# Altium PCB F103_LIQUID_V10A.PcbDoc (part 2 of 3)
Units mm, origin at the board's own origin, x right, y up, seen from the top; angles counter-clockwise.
Board outline 150.1 x 90.1 mm, 2 copper layers (TOP, BOTTOM), stack 1.6 mm thick; 78 components, 80 nets, 341 pads, 418 vias.
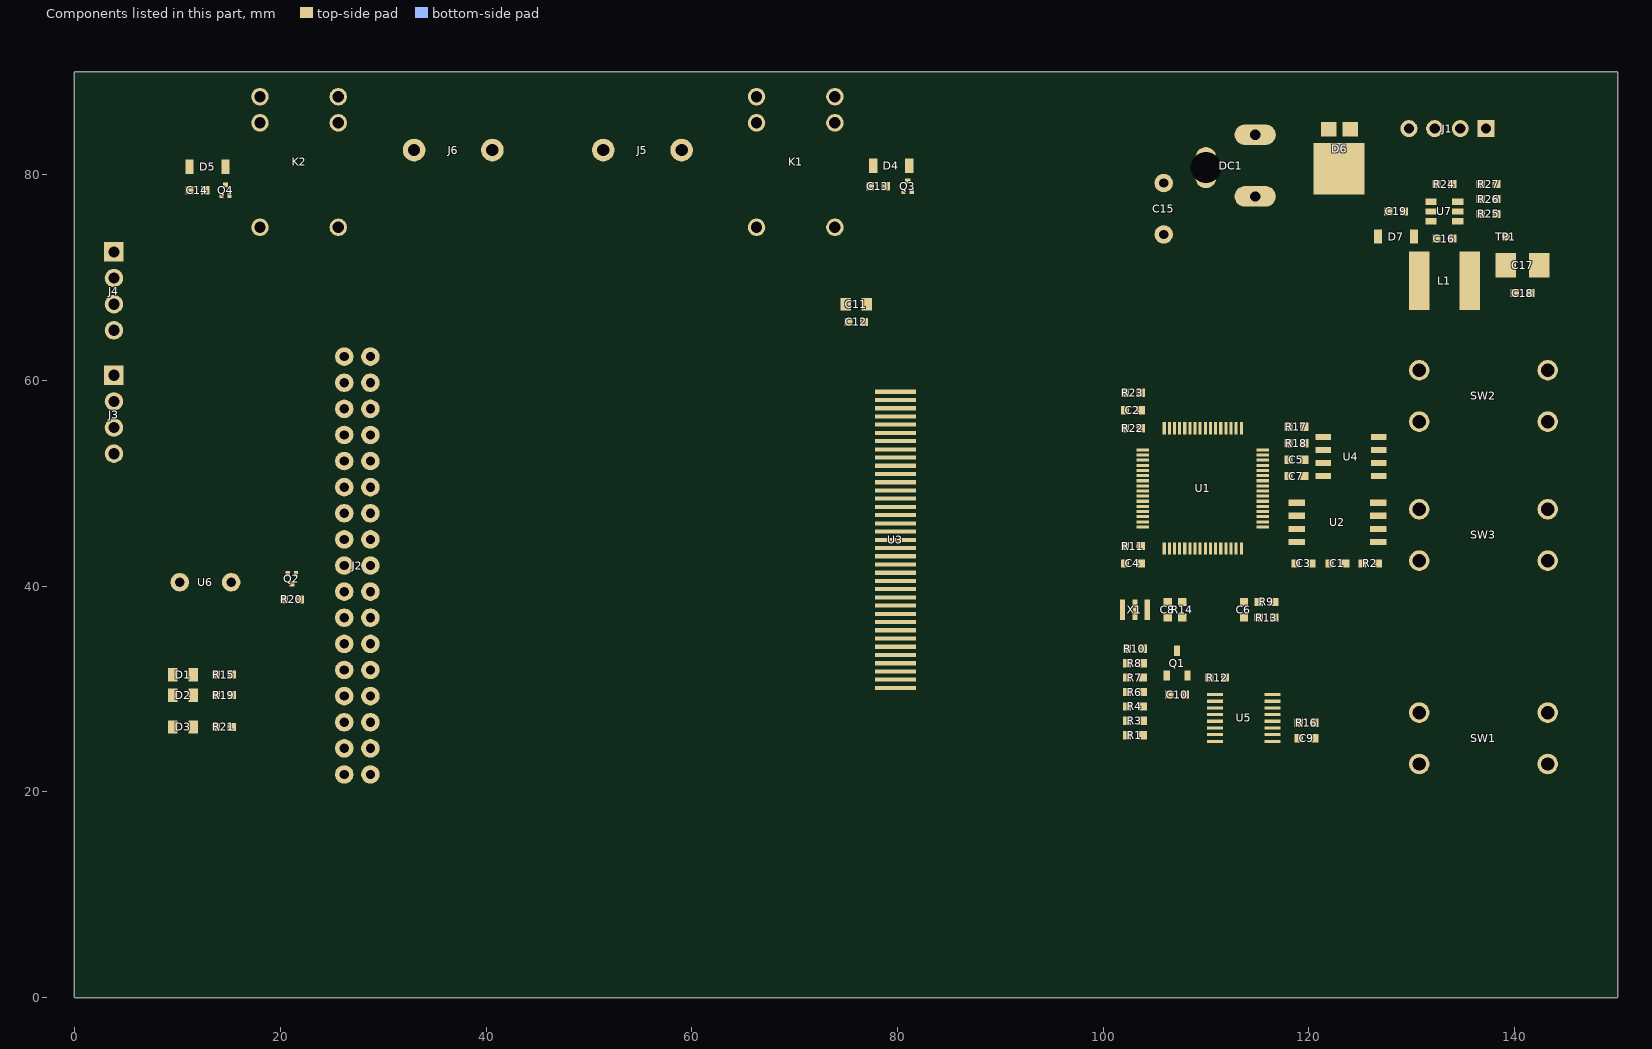
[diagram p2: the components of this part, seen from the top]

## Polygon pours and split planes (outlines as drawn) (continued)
VCC_3.3V on TOP "TOP-VCC_3.3V 26" (solid, pour order 237): 119.947,45.603 119.65,45.865 118.787,45.565 119.65,45.265 119.947,45.527 119.949,45.549 119.95,45.571 119.948,45.593 119.947,45.603
VCC_3.3V on TOP "TOP-VCC_3.3V 27" (solid, pour order 124): 116.298,46.769 116.15,46.9 115.518,46.75 116.15,46.6 116.298,46.731 116.3,46.742 116.3,46.753 116.299,46.764 116.298,46.769
VCC_3.3V on TOP "TOP-VCC_3.3V 28" (solid, pour order 295): 27 vertices, not listed, extent 124.572,41.8 125.626,42.928
VCC_3.3V on TOP "TOP-VCC_3.3V 29" (solid, pour order 256): 121.347,26.787 120.962,27.1 120.498,26.7 120.962,26.3 121.347,26.613 121.353,26.634 121.358,26.656 121.361,26.678 121.362,26.7 121.361,26.722 121.358,26.744 121.353,26.766 121.347,26.787
VCC_3.3V on TOP "TOP-VCC_3.3V 30" (solid, pour order 291): 26 vertices, not listed, extent 119.882,26.046 120.962,27.1
VCC_3.3V on TOP "TOP-VCC_3.3V 31" (solid, pour order 189): 117.423,24.921 117.275,25.052 116.468,24.902 117.275,24.752 117.423,24.883 117.425,24.894 117.425,24.905 117.424,24.916 117.423,24.921
VCC_3.3V on TOP "TOP-VCC_3.3V 32" (solid, pour order 186): 117.423,25.571 117.275,25.702 116.468,25.552 117.275,25.402 117.423,25.533 117.425,25.544 117.425,25.555 117.424,25.566 117.423,25.571
VCC_3.3V on TOP "TOP-VCC_3.3V 33" (solid, pour order 297): 33 vertices, not listed, extent 117.938,24.776 119.438,25.602
VCC_3.3V on TOP "TOP-VCC_3.3V 34" (solid, pour order 303): 33 vertices, not listed, extent 117.888,24.802 119.438,25.679
VCC_3.3V on TOP "TOP-VCC_3.3V 35" (solid, pour order 220): 22 vertices, not listed, extent 137.862,75.4 138.662,76.225
VCC_3.3V on TOP "TOP-VCC_3.3V 36" (solid, pour order 268): 15.175,27.085 14.862,26.7 15.262,26.237 15.662,26.7 15.349,27.085 15.328,27.091 15.306,27.096 15.284,27.099 15.262,27.1 15.24,27.099 15.218,27.096 15.196,27.091 15.175,27.085
VCC_3.3V on TOP "TOP-VCC_3.3V 37" (solid, pour order 269): 15.349,28.616 15.662,29 15.262,29.463 14.862,29 15.175,28.616 15.196,28.609 15.218,28.604 15.24,28.601 15.262,28.6 15.284,28.601 15.306,28.604 15.328,28.609 15.349,28.615 15.349,28.616
VCC_3.3V on TOP "TOP-VCC_3.3V 38" (solid, pour order 266): 15.175,30.184 14.862,29.8 15.262,29.336 15.662,29.8 15.349,30.184 15.328,30.191 15.306,30.196 15.284,30.199 15.262,30.2 15.24,30.199 15.218,30.196 15.196,30.191 15.175,30.185 15.175,30.184
VCC_3.3V on TOP "TOP-VCC_3.3V 39" (solid, pour order 276): 20 vertices, not listed, extent 15.199,30.994 16.156,31.794
VCC_3.3V on TOP "TOP-VCC_3.3V 40" (solid, pour order 271): 15.349,30.61 15.662,30.994 15.262,31.458 14.862,30.994 15.175,30.61 15.196,30.603 15.218,30.598 15.24,30.595 15.262,30.594 15.284,30.595 15.306,30.598 15.328,30.603 15.349,30.61
VCC_3.3V on TOP "TOP-VCC_3.3V 41" (solid, pour order 267): 20.425,37.915 20.738,38.3 20.338,38.763 19.938,38.3 20.251,37.915 20.272,37.909 20.294,37.904 20.316,37.901 20.338,37.9 20.36,37.901 20.382,37.904 20.404,37.909 20.425,37.915
VCC_3.3V on TOP "TOP-VCC_3.3V 42" (solid, pour order 302): 30 vertices, not listed, extent 19.338,38.25 20.738,39.1
VCC_3.3V on TOP "TOP-VCC_3.3V 43" (solid, pour order 353): 25 vertices, not listed, extent 10.155,39.474 11.1,40.418
VCC_3.3V on TOP "TOP-VCC_3.3V 44" (solid, pour order 349): 25 vertices, not listed, extent 3.755,52.835 4.7,53.78
VCC_3.3V on TOP "TOP-VCC_3.3V 45" (solid, pour order 345): 25 vertices, not listed, extent 25.032,54.066 26.264,55.338
VCC_3.3V on TOP "TOP-VCC_3.3V 46" (solid, pour order 272): 117.253,55.403 117.638,55.09 118.102,55.49 117.638,55.89 117.253,55.577 117.247,55.556 117.242,55.534 117.239,55.512 117.238,55.49 117.239,55.468 117.242,55.446 117.247,55.424 117.253,55.403
VCC_3.3V on TOP "TOP-VCC_3.3V 47" (solid, pour order 111): 26 vertices, not listed, extent 104.422,58.585 104.832,59.015
VCC_3.3V on TOP "TOP-VCC_3.3V 48" (solid, pour order 233): 21 vertices, not listed, extent 103.63,58.4 104.462,59.2
VCC_3.3V on TOP "TOP-VCC_3.3V 49" (solid, pour order 110): 25 vertices, not listed, extent 104.422,56.885 104.832,57.315
VCC_3.3V on TOP "TOP-VCC_3.3V 50" (solid, pour order 108): 25 vertices, not listed, extent 104.768,56.885 105.178,57.315
VCC_3.3V on TOP "TOP-VCC_3.3V 51" (solid, pour order 226): 21 vertices, not listed, extent 103.63,56.7 104.462,57.5
VCC_3.3V on TOP "TOP-VCC_3.3V 52" (solid, pour order 128): 105.931,56.098 105.8,55.95 105.95,55.318 106.1,55.95 105.969,56.098 105.958,56.1 105.947,56.1 105.936,56.099 105.931,56.098
VSSA on TOP "TOP-VSSA" (solid, pour order 121): 111.469,42.902 111.6,43.05 111.45,43.682 111.3,43.05 111.431,42.902 111.442,42.9 111.453,42.9 111.464,42.901 111.469,42.902
VSSA on TOP "TOP-VSSA 1" (solid, pour order 235): 21 vertices, not listed, extent 114.338,36.538 115.17,37.338
VSSA on TOP "TOP-VSSA 2" (solid, pour order 234): 21 vertices, not listed, extent 113.668,36.538 114.5,37.338
VSSA on TOP "TOP-VSSA 3" (solid, pour order 293): 31 vertices, not listed, extent 112.773,36.538 114.1,37.465
VDDA on TOP "TOP-VDDA" (solid, pour order 122): 111.969,42.902 112.1,43.05 111.95,43.682 111.8,43.05 111.931,42.902 111.942,42.9 111.953,42.9 111.964,42.901 111.969,42.902
VDDA on TOP "TOP-VDDA 1" (solid, pour order 230): 21 vertices, not listed, extent 114.338,38.062 115.17,38.862
VDDA on TOP "TOP-VDDA 2" (solid, pour order 228): 21 vertices, not listed, extent 113.668,38.062 114.5,38.862
VDDA on TOP "TOP-VDDA 3" (solid, pour order 294): 31 vertices, not listed, extent 112.773,38.062 114.1,38.989
BOOT0 on TOP "TOP-BOOT0" (solid, pour order 172): 104.595,47.781 104.45,47.9 103.825,47.75 104.45,47.6 104.595,47.719 104.597,47.727 104.599,47.736 104.6,47.745 104.6,47.754 104.599,47.763 104.598,47.771 104.595,47.78 104.595,47.781
SWDIO on TOP "TOP-SWDIO" (solid, pour order 341): 25 vertices, not listed, extent 2.9,55.402 3.818,56.32
SWDIO on TOP "TOP-SWDIO 1" (solid, pour order 214): 22 vertices, not listed, extent 101.338,58.4 102.163,59.2
SWDIO on TOP "TOP-SWDIO 2" (solid, pour order 162): 106.919,56.095 106.8,55.95 106.95,55.325 107.1,55.95 106.981,56.095 106.973,56.097 106.964,56.099 106.955,56.1 106.946,56.1 106.937,56.099 106.929,56.098 106.92,56.095 106.919,56.095
SWCLK on TOP "TOP-SWCLK" (solid, pour order 342): 25 vertices, not listed, extent 2.9,57.942 3.818,58.86
SWCLK on TOP "TOP-SWCLK 1" (solid, pour order 282): 23 vertices, not listed, extent 103.25,53.225 104.45,54
SWCLK on TOP "TOP-SWCLK 2" (solid, pour order 279): 27 vertices, not listed, extent 103.16,54.95 104.062,55.94
SWCLK on TOP "TOP-SWCLK 3" (solid, pour order 277): 29 vertices, not listed, extent 103.262,54.362 104.062,55.375
NRST on TOP "TOP-NRST" (solid, pour order 16): 25 vertices, not listed, extent 82.411,53.884 82.825,54.315
NRST on TOP "TOP-NRST 1" (solid, pour order 102): 25 vertices, not listed, extent 108.482,45.795 108.805,46.118
NRST on TOP "TOP-NRST 2" (solid, pour order 229): 21 vertices, not listed, extent 106.268,38.062 107.1,38.862
NRST on TOP "TOP-NRST 3" (solid, pour order 123): 108.969,42.902 109.1,43.05 108.95,43.682 108.8,43.05 108.931,42.902 108.942,42.9 108.953,42.9 108.964,42.901 108.969,42.902
NRST on TOP "TOP-NRST 4" (solid, pour order 165): 108.919,44.395 108.8,44.25 108.95,43.625 109.1,44.25 108.981,44.395 108.973,44.397 108.964,44.399 108.955,44.4 108.946,44.4 108.937,44.399 108.929,44.398 108.92,44.395 108.919,44.395
NRST on TOP "TOP-NRST 5" (solid, pour order 227): 21 vertices, not listed, extent 106.9,38.062 107.732,38.862
NRST on TOP "TOP-NRST 6" (solid, pour order 207): 20 vertices, not listed, extent 107.668,38.062 108.481,38.862
OSC_IN on TOP "TOP-OSC_IN" (solid, pour order 304): 26 vertices, not listed, extent 101.65,36.7 102.302,38.802
OSC_IN on TOP "TOP-OSC_IN 1" (solid, pour order 161): 107.981,42.905 108.1,43.05 107.95,43.675 107.8,43.05 107.919,42.905 107.927,42.903 107.936,42.901 107.945,42.9 107.954,42.9 107.963,42.901 107.971,42.902 107.98,42.905 107.981,42.905
OSC_OUT on TOP "TOP-OSC_OUT" (solid, pour order 300): 27 vertices, not listed, extent 103.948,36.7 104.55,38.852
OSC_OUT on TOP "TOP-OSC_OUT 1" (solid, pour order 171): 108.481,42.905 108.6,43.05 108.45,43.675 108.3,43.05 108.419,42.905 108.427,42.903 108.436,42.901 108.445,42.9 108.454,42.9 108.463,42.901 108.471,42.902 108.48,42.905 108.481,42.905
LED1 on TOP "TOP-LED1" (solid, pour order 310): 24 vertices, not listed, extent 8.42,28.75 9.545,30.05
LED1 on TOP "TOP-LED1 1" (solid, pour order 79): 26 vertices, not listed, extent 7.675,29.185 8.089,29.616
LED1 on TOP "TOP-LED1 2" (solid, pour order 84): 25 vertices, not listed, extent 112.284,46.075 112.715,46.489
LED1 on TOP "TOP-LED1 3" (solid, pour order 152): 104.595,50.781 104.45,50.9 103.825,50.75 104.45,50.6 104.595,50.719 104.597,50.727 104.599,50.736 104.6,50.745 104.6,50.754 104.599,50.763 104.598,50.771 104.595,50.78 104.595,50.781
USART1_TX on TOP "TOP-USART1_TX" (solid, pour order 343): 25 vertices, not listed, extent 3.782,66.52 4.7,67.438
USART1_TX on TOP "TOP-USART1_TX 1" (solid, pour order 149): 108.919,56.095 108.8,55.95 108.95,55.325 109.1,55.95 108.981,56.095 108.973,56.097 108.964,56.099 108.955,56.1 108.946,56.1 108.937,56.099 108.929,56.098 108.92,56.095 108.919,56.095
N17026724 on TOP "TOP-N17026724" (solid, pour order 216): 22 vertices, not listed, extent 12.938,25.9 13.763,26.7
N17026724 on TOP "TOP-N17026724 1" (solid, pour order 312): 24 vertices, not listed, extent 11.495,25.65 12.62,26.95
USART1_RX on TOP "TOP-USART1_RX" (solid, pour order 344): 25 vertices, not listed, extent 3.782,64.862 4.7,65.78
USART1_RX on TOP "TOP-USART1_RX 1" (solid, pour order 173): 108.419,56.095 108.3,55.95 108.45,55.325 108.6,55.95 108.481,56.095 108.473,56.097 108.464,56.099 108.455,56.1 108.446,56.1 108.437,56.099 108.429,56.098 108.42,56.095 108.419,56.095
SPI1_MISO on TOP "TOP-SPI1_MISO" (solid, pour order 239): 23 vertices, not listed, extent 125.615,45.265 126.775,45.865
SPI1_MISO on TOP "TOP-SPI1_MISO 1" (solid, pour order 150): 116.295,48.281 116.15,48.4 115.525,48.25 116.15,48.1 116.295,48.219 116.297,48.227 116.299,48.236 116.3,48.245 116.3,48.254 116.299,48.263 116.298,48.271 116.295,48.28 116.295,48.281
SPI1_MOSI on TOP "TOP-SPI1_MOSI" (solid, pour order 169): 116.295,48.781 116.15,48.9 115.525,48.75 116.15,48.6 116.295,48.719 116.297,48.727 116.299,48.736 116.3,48.745 116.3,48.754 116.299,48.763 116.298,48.771 116.295,48.78 116.295,48.781
SPI1_MOSI on TOP "TOP-SPI1_MOSI 1" (solid, pour order 299): 26 vertices, not listed, extent 117.948,47.805 119.65,48.552
SPI1_SCK on TOP "TOP-SPI1_SCK" (solid, pour order 224): 21 vertices, not listed, extent 117.75,46.535 118.875,47.135
SPI1_SCK on TOP "TOP-SPI1_SCK 1" (solid, pour order 170): 116.295,47.781 116.15,47.9 115.525,47.75 116.15,47.6 116.295,47.719 116.297,47.727 116.299,47.736 116.3,47.745 116.3,47.754 116.299,47.763 116.298,47.771 116.295,47.78 116.295,47.781
KEY0 on TOP "TOP-KEY0" (solid, pour order 364): 25 vertices, not listed, extent 141.878,55.293 143.275,56.707
KEY0 on TOP "TOP-KEY0 1" (solid, pour order 372): 26 vertices, not listed, extent 130.037,54.578 131.457,56.025
KEY0 on TOP "TOP-KEY0 2" (solid, pour order 363): 25 vertices, not listed, extent 130.725,55.293 132.122,56.707
KEY0 on TOP "TOP-KEY0 3" (solid, pour order 156): 116.295,49.781 116.15,49.9 115.525,49.75 116.15,49.6 116.295,49.719 116.297,49.727 116.299,49.736 116.3,49.745 116.3,49.754 116.299,49.763 116.298,49.771 116.295,49.78 116.295,49.781
KEY1 on TOP "TOP-KEY1" (solid, pour order 362): 25 vertices, not listed, extent 130.725,41.767 132.122,43.181
KEY1 on TOP "TOP-KEY1 1" (solid, pour order 367): 25 vertices, not listed, extent 143.232,42.456 144.25,43.473
KEY1 on TOP "TOP-KEY1 2" (solid, pour order 361): 25 vertices, not listed, extent 141.878,41.767 143.275,43.181
KEY1 on TOP "TOP-KEY1 3" (solid, pour order 177): 104.595,52.781 104.45,52.9 103.825,52.75 104.45,52.6 104.595,52.719 104.597,52.727 104.599,52.736 104.6,52.745 104.6,52.754 104.599,52.763 104.598,52.771 104.595,52.78 104.595,52.781
WK_UP on TOP "TOP-WK_UP" (solid, pour order 365): 25 vertices, not listed, extent 130.725,21.993 132.122,23.407
WK_UP on TOP "TOP-WK_UP 1" (solid, pour order 368): 25 vertices, not listed, extent 143.232,22.682 144.25,23.7
WK_UP on TOP "TOP-WK_UP 2" (solid, pour order 366): 25 vertices, not listed, extent 141.878,21.993 143.275,23.407
WK_UP on TOP "TOP-WK_UP 3" (solid, pour order 181): 112.481,42.905 112.6,43.05 112.45,43.675 112.3,43.05 112.419,42.905 112.427,42.903 112.436,42.901 112.445,42.9 112.454,42.9 112.463,42.901 112.471,42.902 112.48,42.905 112.481,42.905
LED0 on TOP "TOP-LED0" (solid, pour order 314): 24 vertices, not listed, extent 8.414,30.744 9.545,32.044
LED0 on TOP "TOP-LED0 1" (solid, pour order 159): 109.419,56.095 109.3,55.95 109.45,55.325 109.6,55.95 109.481,56.095 109.473,56.097 109.464,56.099 109.455,56.1 109.446,56.1 109.437,56.099 109.429,56.098 109.42,56.095 109.419,56.095
IIC_SDA on TOP "TOP-IIC_SDA" (solid, pour order 203): 17 vertices, not listed, extent 120.44,54.258 121.425,54.762
IIC_SDA on TOP "TOP-IIC_SDA 1" (solid, pour order 158): 104.595,51.781 104.45,51.9 103.825,51.75 104.45,51.6 104.595,51.719 104.597,51.727 104.599,51.736 104.6,51.745 104.6,51.754 104.599,51.763 104.598,51.771 104.595,51.78 104.595,51.781
IIC_SCL on TOP "TOP-IIC_SCL" (solid, pour order 206): 21 vertices, not listed, extent 120.35,52.94 121.425,53.54
IIC_SCL on TOP "TOP-IIC_SCL 1" (solid, pour order 139): 104.595,51.281 104.45,51.4 103.825,51.25 104.45,51.1 104.595,51.219 104.597,51.227 104.599,51.236 104.6,51.245 104.6,51.254 104.599,51.263 104.598,51.271 104.595,51.28 104.595,51.281
F_CS on TOP "TOP-F_CS" (solid, pour order 218): 22 vertices, not listed, extent 126.35,42.175 127.15,43
F_CS on TOP "TOP-F_CS 1" (solid, pour order 355): 23 vertices, not listed, extent 125.971,43.258 127.529,44.32
F_CS on TOP "TOP-F_CS 2" (solid, pour order 225): 21 vertices, not listed, extent 125.645,43.995 126.775,44.595
F_CS on TOP "TOP-F_CS 3" (solid, pour order 138): 116.295,47.281 116.15,47.4 115.525,47.25 116.15,47.1 116.295,47.219 116.297,47.227 116.299,47.236 116.3,47.245 116.3,47.254 116.299,47.263 116.298,47.271 116.295,47.28 116.295,47.281
CTL_BEEP on TOP "TOP-CTL_BEEP" (solid, pour order 201): 26 vertices, not listed, extent 21.198,40.95 21.7,41.583
CTL_BEEP on TOP "TOP-CTL_BEEP 1" (solid, pour order 137): 107.919,56.095 107.8,55.95 107.95,55.325 108.1,55.95 107.981,56.095 107.973,56.097 107.964,56.099 107.955,56.1 107.946,56.1 107.937,56.099 107.929,56.098 107.92,56.095 107.919,56.095
N17064279 on TOP "TOP-N17064279" (solid, pour order 270): 21.775,39.485 21.462,39.1 21.862,38.636 22.262,39.1 21.949,39.485 21.928,39.491 21.906,39.496 21.884,39.499 21.862,39.5 21.84,39.499 21.818,39.496 21.796,39.491 21.775,39.485
N17064279 on TOP "TOP-N17064279 1" (solid, pour order 371): 30 vertices, not listed, extent 15.137,39.685 16.541,41.01
USART2_TX on TOP "TOP-USART2_TX" (solid, pour order 283): 23 vertices, not listed, extent 113.425,43.05 114.2,44.25
N17026648 on TOP "TOP-N17026648" (solid, pour order 311): 24 vertices, not listed, extent 11.495,28.75 12.62,30.05
N17026648 on TOP "TOP-N17026648 1" (solid, pour order 209): 22 vertices, not listed, extent 12.938,29 13.763,29.8
N17026623 on TOP "TOP-N17026623" (solid, pour order 215): 22 vertices, not listed, extent 12.938,30.994 13.763,31.794
N17026623 on TOP "TOP-N17026623 1" (solid, pour order 313): 24 vertices, not listed, extent 11.495,30.744 12.62,32.044
USART2_RX on TOP "TOP-USART2_RX" (solid, pour order 298): 25 vertices, not listed, extent 134.732,83.675 135.575,84.518
USART2_RX on TOP "TOP-USART2_RX 1" (solid, pour order 281): 23 vertices, not listed, extent 114.95,45 116.15,45.775
N17081273 on TOP "TOP-N17081273" (solid, pour order 360): 29 vertices, not listed, extent 80.749,79.65 81.55,81.6
N17081273 on TOP "TOP-N17081273 1" (solid, pour order 289): 18 vertices, not listed, extent 80.75,80.837 81.55,82.05
N17081273 on TOP "TOP-N17081273 2" (solid, pour order 309): 26 vertices, not listed, extent 73.856,84.459 75.017,85.661
LCD_D15 on TOP "TOP-LCD_D15" (solid, pour order 317): 25 vertices, not listed, extent 28.715,46.446 29.971,47.718
LCD_D15 on TOP "TOP-LCD_D15 1" (solid, pour order 65): 26 vertices, not listed, extent 84.811,53.087 85.225,53.518
LCD_D15 on TOP "TOP-LCD_D15 2" (solid, pour order 76): 26 vertices, not listed, extent 85.275,67.675 85.689,68.106
LCD_D15 on TOP "TOP-LCD_D15 3" (solid, pour order 148): 111.919,56.095 111.8,55.95 111.95,55.325 112.1,55.95 111.981,56.095 111.973,56.097 111.964,56.099 111.955,56.1 111.946,56.1 111.937,56.099 111.929,56.098 111.92,56.095 111.919,56.095
LCD_D14 on TOP "TOP-LCD_D14" (solid, pour order 336): 25 vertices, not listed, extent 26.182,44.524 27.1,45.442
LCD_D14 on TOP "TOP-LCD_D14 1" (solid, pour order 60): 26 vertices, not listed, extent 84.811,52.286 85.225,52.717
LCD_D14 on TOP "TOP-LCD_D14 2" (solid, pour order 74): 26 vertices, not listed, extent 85.275,68.411 85.689,68.842
LCD_D14 on TOP "TOP-LCD_D14 3" (solid, pour order 175): 112.419,56.095 112.3,55.95 112.45,55.325 112.6,55.95 112.481,56.095 112.473,56.097 112.464,56.099 112.455,56.1 112.446,56.1 112.437,56.099 112.429,56.098 112.42,56.095 112.419,56.095
LCD_LEDK4 on TOP "TOP-LCD_LEDK4" (solid, pour order 243): 18 vertices, not listed, extent 101.538,33.5 102.388,34.3
LCD_D6 on TOP "TOP-LCD_D6" (solid, pour order 87): 26 vertices, not listed, extent 76.075,57.887 76.489,58.318
LCD_D6 on TOP "TOP-LCD_D6 1" (solid, pour order 75): 26 vertices, not listed, extent 75.711,57.887 76.125,58.318
LCD_D6 on TOP "TOP-LCD_D6 2" (solid, pour order 168): 103.105,48.719 103.25,48.6 103.875,48.75 103.25,48.9 103.105,48.781 103.103,48.773 103.101,48.764 103.1,48.755 103.1,48.746 103.101,48.737 103.102,48.729 103.105,48.72 103.105,48.719
IM0 on TOP "TOP-IM0" (solid, pour order 210): 22 vertices, not listed, extent 101.938,26.1 102.738,26.925
IM0 on TOP "TOP-IM0 1" (solid, pour order 212): 22 vertices, not listed, extent 101.938,25.475 102.738,26.3
IM0 on TOP "TOP-IM0 2" (solid, pour order 211): 22 vertices, not listed, extent 101.538,25.1 102.363,25.9
LCD_D12 on TOP "TOP-LCD_D12" (solid, pour order 337): 25 vertices, not listed, extent 26.182,41.984 27.1,42.902
LCD_D12 on TOP "TOP-LCD_D12 1" (solid, pour order 63): 26 vertices, not listed, extent 84.811,50.687 85.225,51.117
LCD_D12 on TOP "TOP-LCD_D12 2" (solid, pour order 78): 26 vertices, not listed, extent 85.275,69.885 85.689,70.316
LCD_D12 on TOP "TOP-LCD_D12 3" (solid, pour order 144): 113.419,56.095 113.3,55.95 113.45,55.325 113.6,55.95 113.481,56.095 113.473,56.097 113.464,56.099 113.455,56.1 113.446,56.1 113.437,56.099 113.429,56.098 113.42,56.095 113.419,56.095
LCD_LEDK1 on TOP "TOP-LCD_LEDK1" (solid, pour order 240): 18 vertices, not listed, extent 101.538,29.3 102.388,30.1
LCD_D7 on TOP "TOP-LCD_D7" (solid, pour order 61): 26 vertices, not listed, extent 76.075,58.686 76.489,59.117
LCD_D7 on TOP "TOP-LCD_D7 1" (solid, pour order 135): 103.105,48.219 103.25,48.1 103.875,48.25 103.25,48.4 103.105,48.281 103.103,48.273 103.101,48.264 103.1,48.255 103.1,48.246 103.101,48.237 103.102,48.229 103.105,48.22 103.105,48.219
LCD_LEDK2 on TOP "TOP-LCD_LEDK2" (solid, pour order 241): 18 vertices, not listed, extent 101.538,30.7 102.388,31.5
Y+ on TOP "TOP-Y+" (solid, pour order 194): 109.98,28.121 110.125,28.002 110.925,28.152 110.125,28.302 109.98,28.183 109.978,28.175 109.976,28.166 109.975,28.157 109.975,28.148 109.976,28.14 109.977,28.131 109.98,28.122 109.98,28.121
LCD_D5 on TOP "TOP-LCD_D5" (solid, pour order 66): 26 vertices, not listed, extent 76.075,57.087 76.489,57.517
LCD_D5 on TOP "TOP-LCD_D5 1" (solid, pour order 38): 26 vertices, not listed, extent 75.711,57.087 76.125,57.517
LCD_D5 on TOP "TOP-LCD_D5 2" (solid, pour order 134): 103.105,49.219 103.25,49.1 103.875,49.25 103.25,49.4 103.105,49.281 103.103,49.273 103.101,49.264 103.1,49.255 103.1,49.246 103.101,49.237 103.102,49.229 103.105,49.22 103.105,49.219
LCD_LEDA on TOP "TOP-LCD_LEDA" (solid, pour order 244): 18 vertices, not listed, extent 101.538,27.9 102.388,28.7
X- on TOP "TOP-X-" (solid, pour order 190): 109.98,27.471 110.125,27.352 110.925,27.502 110.125,27.652 109.98,27.533 109.978,27.525 109.976,27.516 109.975,27.507 109.975,27.498 109.976,27.49 109.977,27.481 109.98,27.472 109.98,27.471
LCD_D11 on TOP "TOP-LCD_D11" (solid, pour order 324): 25 vertices, not listed, extent 28.715,41.366 29.971,42.638
LCD_D11 on TOP "TOP-LCD_D11 1" (solid, pour order 89): 26 vertices, not listed, extent 84.811,49.886 85.225,50.317
LCD_D11 on TOP "TOP-LCD_D11 2" (solid, pour order 143): 114.805,52.219 114.95,52.1 115.575,52.25 114.95,52.4 114.805,52.281 114.803,52.273 114.801,52.264 114.8,52.255 114.8,52.246 114.801,52.237 114.802,52.229 114.805,52.22 114.805,52.219
LCD_D11 on TOP "TOP-LCD_D11 3" (solid, pour order 7): 25 vertices, not listed, extent 110.275,50.184 110.689,50.615
LCD_D9 on TOP "TOP-LCD_D9" (solid, pour order 323): 25 vertices, not listed, extent 28.715,38.826 29.971,40.098
LCD_D9 on TOP "TOP-LCD_D9 1" (solid, pour order 21): 26 vertices, not listed, extent 85.175,45.885 85.589,46.316
LCD_D9 on TOP "TOP-LCD_D9 2" (solid, pour order 131): 103.105,46.719 103.25,46.6 103.875,46.75 103.25,46.9 103.105,46.781 103.103,46.773 103.101,46.764 103.1,46.755 103.1,46.746 103.101,46.737 103.102,46.729 103.105,46.72 103.105,46.719
LCD_D9 on TOP "TOP-LCD_D9 3" (solid, pour order 59): 26 vertices, not listed, extent 84.811,48.286 85.225,48.717
X+ on TOP "TOP-X+" (solid, pour order 193): 109.98,28.771 110.125,28.652 110.925,28.802 110.125,28.952 109.98,28.833 109.978,28.825 109.976,28.816 109.975,28.807 109.975,28.798 109.976,28.79 109.977,28.781 109.98,28.772 109.98,28.771
N170859511 on TOP "TOP-N170859511" (solid, pour order 278): 26 vertices, not listed, extent 109.798,30.7 110.738,31.602
N17085874 on TOP "TOP-N17085874" (solid, pour order 292): 25 vertices, not listed, extent 106.2,33.2 107.261,34.2
N17085874 on TOP "TOP-N17085874 1" (solid, pour order 263): 104.646,33.987 104.262,34.3 103.798,33.9 104.262,33.5 104.646,33.813 104.653,33.834 104.658,33.856 104.661,33.878 104.662,33.9 104.661,33.922 104.658,33.944 104.653,33.966 104.647,33.987 104.646,33.987
N17085874 on TOP "TOP-N17085874 2" (solid, pour order 258): 103.949,33.115 104.262,33.5 103.862,33.964 103.462,33.5 103.775,33.115 103.796,33.109 103.818,33.104 103.84,33.101 103.862,33.1 103.884,33.101 103.906,33.104 103.928,33.109 103.949,33.115
N17085874 on TOP "TOP-N17085874 3" (solid, pour order 247): 103.775,33.285 103.462,32.9 103.862,32.437 104.262,32.9 103.949,33.285 103.928,33.291 103.906,33.296 103.884,33.299 103.862,33.3 103.84,33.299 103.818,33.296 103.796,33.291 103.775,33.285
N17085874 on TOP "TOP-N17085874 4" (solid, pour order 257): 103.949,31.715 104.262,32.1 103.862,32.564 103.462,32.1 103.775,31.715 103.796,31.709 103.818,31.704 103.84,31.701 103.862,31.7 103.884,31.701 103.906,31.704 103.928,31.709 103.949,31.715
N17085874 on TOP "TOP-N17085874 5" (solid, pour order 255): 103.775,31.885 103.462,31.5 103.862,31.036 104.262,31.5 103.949,31.885 103.928,31.891 103.906,31.896 103.884,31.899 103.862,31.9 103.84,31.899 103.818,31.896 103.796,31.891 103.775,31.885
N17085874 on TOP "TOP-N17085874 6" (solid, pour order 250): 103.949,30.315 104.262,30.7 103.862,31.163 103.462,30.7 103.775,30.315 103.796,30.309 103.818,30.304 103.84,30.301 103.862,30.3 103.884,30.301 103.906,30.304 103.928,30.309 103.949,30.315
N17085874 on TOP "TOP-N17085874 7" (solid, pour order 259): 103.775,30.485 103.462,30.1 103.862,29.636 104.262,30.1 103.949,30.485 103.928,30.491 103.906,30.496 103.884,30.499 103.862,30.5 103.84,30.499 103.818,30.496 103.796,30.491 103.775,30.485
LCD_D1 on TOP "TOP-LCD_D1" (solid, pour order 2): 25 vertices, not listed, extent 75.975,30.686 76.389,31.117
LCD_D1 on TOP "TOP-LCD_D1 1" (solid, pour order 15): 25 vertices, not listed, extent 89.111,30.686 89.525,31.117
LCD_D1 on TOP "TOP-LCD_D1 2" (solid, pour order 4): 25 vertices, not listed, extent 110.275,47.975 110.689,48.406
LCD_D1 on TOP "TOP-LCD_D1 3" (solid, pour order 151): 114.805,50.719 114.95,50.6 115.575,50.75 114.95,50.9 114.805,50.781 114.803,50.773 114.801,50.764 114.8,50.755 114.8,50.746 114.801,50.737 114.802,50.729 114.805,50.72 114.805,50.719
Y- on TOP "TOP-Y-" (solid, pour order 191): 109.98,26.821 110.125,26.702 110.925,26.852 110.125,27.002 109.98,26.883 109.978,26.875 109.976,26.866 109.975,26.857 109.975,26.848 109.976,26.84 109.977,26.831 109.98,26.822 109.98,26.821
LCD_LEDK3 on TOP "TOP-LCD_LEDK3" (solid, pour order 242): 18 vertices, not listed, extent 101.538,32.1 102.388,32.9
LCD_D8 on TOP "TOP-LCD_D8" (solid, pour order 329): 25 vertices, not listed, extent 26.182,36.904 27.1,37.822
LCD_D8 on TOP "TOP-LCD_D8 1" (solid, pour order 132): 103.105,47.219 103.25,47.1 103.875,47.25 103.25,47.4 103.105,47.281 103.103,47.273 103.101,47.264 103.1,47.255 103.1,47.246 103.101,47.237 103.102,47.229 103.105,47.22 103.105,47.219
LCD_BL on TOP "TOP-LCD_BL" (solid, pour order 136): 103.105,52.219 103.25,52.1 103.875,52.25 103.25,52.4 103.105,52.281 103.103,52.273 103.101,52.264 103.1,52.255 103.1,52.246 103.101,52.237 103.102,52.229 103.105,52.22 103.105,52.219
LCD_BL on TOP "TOP-LCD_BL 1" (solid, pour order 119): 29 vertices, not listed, extent 94.475,51.985 94.939,52.435
LCD_BL on TOP "TOP-LCD_BL 2" (solid, pour order 103): 25 vertices, not listed, extent 94.482,44.095 94.805,44.418
LCD_BL on TOP "TOP-LCD_BL 3" (solid, pour order 223): 22 vertices, not listed, extent 111.462,31.075 112.262,31.9
LCD_D0 on TOP "TOP-LCD_D0" (solid, pour order 44): 25 vertices, not listed, extent 75.975,29.887 76.389,30.318
LCD_D0 on TOP "TOP-LCD_D0 1" (solid, pour order 1): 25 vertices, not listed, extent 110.275,47.238 110.689,47.669
LCD_D0 on TOP "TOP-LCD_D0 2" (solid, pour order 176): 114.805,50.219 114.95,50.1 115.575,50.25 114.95,50.4 114.805,50.281 114.803,50.273 114.801,50.264 114.8,50.255 114.8,50.246 114.801,50.237 114.802,50.229 114.805,50.22 114.805,50.219
LCD_D0 on TOP "TOP-LCD_D0 3" (solid, pour order 53): 25 vertices, not listed, extent 89.111,29.887 89.525,30.318
LCD_D10 on TOP "TOP-LCD_D10" (solid, pour order 339): 25 vertices, not listed, extent 26.182,39.444 27.1,40.362
LCD_D10 on TOP "TOP-LCD_D10 1" (solid, pour order 62): 26 vertices, not listed, extent 84.811,49.087 85.225,49.518
LCD_D10 on TOP "TOP-LCD_D10 2" (solid, pour order 141): 114.805,51.719 114.95,51.6 115.575,51.75 114.95,51.9 114.805,51.781 114.803,51.773 114.801,51.764 114.8,51.755 114.8,51.746 114.801,51.737 114.802,51.729 114.805,51.72 114.805,51.719
LCD_D10 on TOP "TOP-LCD_D10 3" (solid, pour order 6): 25 vertices, not listed, extent 110.275,49.448 110.689,49.879
LCD_CS on TOP "TOP-LCD_CS" (solid, pour order 42): 25 vertices, not listed, extent 89.111,34.686 89.525,35.117
LCD_CS on TOP "TOP-LCD_CS 1" (solid, pour order 34): 26 vertices, not listed, extent 93.975,62.675 94.389,63.106
LCD_CS on TOP "TOP-LCD_CS 2" (solid, pour order 174): 109.919,56.095 109.8,55.95 109.95,55.325 110.1,55.95 109.981,56.095 109.973,56.097 109.964,56.099 109.955,56.1 109.946,56.1 109.937,56.099 109.929,56.098 109.92,56.095 109.919,56.095
LCD_D13 on TOP "TOP-LCD_D13" (solid, pour order 322): 25 vertices, not listed, extent 28.715,43.906 29.971,45.178
LCD_D13 on TOP "TOP-LCD_D13 1" (solid, pour order 88): 26 vertices, not listed, extent 84.811,51.487 85.225,51.918
LCD_D13 on TOP "TOP-LCD_D13 2" (solid, pour order 67): 26 vertices, not listed, extent 85.275,69.148 85.689,69.579
LCD_D13 on TOP "TOP-LCD_D13 3" (solid, pour order 160): 112.919,56.095 112.8,55.95 112.95,55.325 113.1,55.95 112.981,56.095 112.973,56.097 112.964,56.099 112.955,56.1 112.946,56.1 112.937,56.099 112.929,56.098 112.92,56.095 112.919,56.095
LCD_RS on TOP "TOP-LCD_RS" (solid, pour order 14): 25 vertices, not listed, extent 89.111,35.487 89.525,35.917
LCD_RS on TOP "TOP-LCD_RS 1" (solid, pour order 39): 26 vertices, not listed, extent 93.975,63.411 94.389,63.842
LCD_RS on TOP "TOP-LCD_RS 2" (solid, pour order 146): 110.419,56.095 110.3,55.95 110.45,55.325 110.6,55.95 110.481,56.095 110.473,56.097 110.464,56.099 110.455,56.1 110.446,56.1 110.437,56.099 110.429,56.098 110.42,56.095 110.419,56.095
LCD_RD on TOP "TOP-LCD_RD" (solid, pour order 10): 25 vertices, not listed, extent 89.111,37.086 89.525,37.517
LCD_RD on TOP "TOP-LCD_RD 1" (solid, pour order 35): 26 vertices, not listed, extent 93.975,64.885 94.389,65.316
LCD_RD on TOP "TOP-LCD_RD 2" (solid, pour order 154): 111.419,56.095 111.3,55.95 111.45,55.325 111.6,55.95 111.481,56.095 111.473,56.097 111.464,56.099 111.455,56.1 111.446,56.1 111.437,56.099 111.429,56.098 111.42,56.095 111.419,56.095
LCD_WR on TOP "TOP-LCD_WR" (solid, pour order 30): 25 vertices, not listed, extent 89.111,36.287 89.525,36.718
LCD_WR on TOP "TOP-LCD_WR 1" (solid, pour order 36): 26 vertices, not listed, extent 93.975,64.148 94.389,64.579
LCD_WR on TOP "TOP-LCD_WR 2" (solid, pour order 140): 110.919,56.095 110.8,55.95 110.95,55.325 111.1,55.95 110.981,56.095 110.973,56.097 110.964,56.099 110.955,56.1 110.946,56.1 110.937,56.099 110.929,56.098 110.92,56.095 110.919,56.095
VCC_12V on TOP "TOP-VCC_12V" (solid, pour order 412): 18 vertices, not listed, extent 16.3,72.4 130.8,83.2
VCC_12V on TOP "TOP-VCC_12V 1" (solid, pour order 222): 22 vertices, not listed, extent 131.638,78.7 132.463,79.5
VCC_12V on TOP "TOP-VCC_12V 2" (solid, pour order 205): 131.053,76.402 131.35,76.14 131.964,76.44 131.35,76.74 131.053,76.478 131.051,76.456 131.05,76.434 131.052,76.412 131.053,76.402
VCC_12V on TOP "TOP-VCC_12V 3" (solid, pour order 306): 25 vertices, not listed, extent 65.699,83.963 66.901,85.124
VCC_12V on TOP "TOP-VCC_12V 4" (solid, pour order 307): 25 vertices, not listed, extent 16.903,74.299 18.063,75.501
VCC_12V on TOP "TOP-VCC_12V 5" (solid, pour order 253): 77.425,78.116 77.738,78.5 77.338,78.963 76.938,78.5 77.251,78.116 77.251,78.115 77.272,78.109 77.294,78.104 77.316,78.101 77.338,78.1 77.36,78.101 77.382,78.104 77.404,78.109 77.425,78.115 77.425,78.116
VCC_12V on TOP "TOP-VCC_12V 6" (solid, pour order 252): 77.251,79.684 76.938,79.3 77.338,78.836 77.738,79.3 77.425,79.684 77.404,79.691 77.382,79.696 77.36,79.699 77.338,79.7 77.316,79.699 77.294,79.696 77.272,79.691 77.251,79.685 77.251,79.684
VCC_12V on TOP "TOP-VCC_12V 7" (solid, pour order 358): 21 vertices, not listed, extent 76.55,80.2 77.713,81.6
VCC_12V on TOP "TOP-VCC_12V 8" (solid, pour order 373): 32 vertices, not listed, extent 77.084,79.488 78.05,81.6
VCC_12V on TOP "TOP-VCC_12V 9" (solid, pour order 284): 11.063,81.884 10.75,81.5 11.15,80.737 11.55,81.5 11.237,81.884 11.216,81.891 11.194,81.896 11.172,81.899 11.15,81.9 11.128,81.899 11.106,81.896 11.084,81.891 11.063,81.885 11.063,81.884
VCC_12V on TOP "TOP-VCC_12V 10" (solid, pour order 285): 11.237,79.715 11.55,80.1 11.15,80.864 10.75,80.1 11.063,79.715 11.084,79.709 11.106,79.704 11.128,79.701 11.15,79.7 11.172,79.701 11.194,79.704 11.216,79.709 11.237,79.715
VCC_12V on TOP "TOP-VCC_12V 11" (solid, pour order 254): 11.237,77.716 11.55,78.1 11.15,78.564 10.75,78.1 11.063,77.716 11.084,77.709 11.106,77.704 11.128,77.701 11.15,77.7 11.172,77.701 11.194,77.704 11.216,77.709 11.237,77.715 11.237,77.716
VCC_12V on TOP "TOP-VCC_12V 12" (solid, pour order 260): 11.063,79.284 10.75,78.9 11.15,78.437 11.55,78.9 11.237,79.284 11.216,79.291 11.194,79.296 11.172,79.299 11.15,79.3 11.128,79.299 11.106,79.296 11.084,79.291 11.063,79.285 11.063,79.284
VCC_12V on TOP "TOP-VCC_12V 13" (solid, pour order 308): 25 vertices, not listed, extent 16.903,84.459 18.063,85.661
LCD_D2 on TOP "TOP-LCD_D2" (solid, pour order 13): 25 vertices, not listed, extent 75.975,31.487 76.389,31.918
LCD_D2 on TOP "TOP-LCD_D2 1" (solid, pour order 0): 25 vertices, not listed, extent 110.275,48.711 110.689,49.142
LCD_D2 on TOP "TOP-LCD_D2 2" (solid, pour order 145): 114.805,51.219 114.95,51.1 115.575,51.25 114.95,51.4 114.805,51.281 114.803,51.273 114.801,51.264 114.8,51.255 114.8,51.246 114.801,51.237 114.802,51.229 114.805,51.22 114.805,51.219
LCD_D2 on TOP "TOP-LCD_D2 3" (solid, pour order 3): 25 vertices, not listed, extent 89.111,31.487 89.525,31.918
LCD_D4 on TOP "TOP-LCD_D4" (solid, pour order 334): 25 vertices, not listed, extent 26.182,31.824 27.1,32.742
LCD_D4 on TOP "TOP-LCD_D4 1" (solid, pour order 5): 25 vertices, not listed, extent 90.211,46.687 90.625,47.118
LCD_D4 on TOP "TOP-LCD_D4 2" (solid, pour order 101): 25 vertices, not listed, extent 90.582,50.395 90.905,50.718
LCD_D4 on TOP "TOP-LCD_D4 3" (solid, pour order 133): 103.105,49.719 103.25,49.6 103.875,49.75 103.25,49.9 103.105,49.781 103.103,49.773 103.101,49.764 103.1,49.755 103.1,49.746 103.101,49.737 103.102,49.729 103.105,49.72 103.105,49.719
LCD_D3 on TOP "TOP-LCD_D3" (solid, pour order 90): 25 vertices, not listed, extent 75.975,32.286 76.389,32.718
LCD_D3 on TOP "TOP-LCD_D3 1" (solid, pour order 105): 25 vertices, not listed, extent 105.395,49.682 105.718,50.005
LCD_D3 on TOP "TOP-LCD_D3 2" (solid, pour order 178): 104.595,50.281 104.45,50.4 103.825,50.25 104.45,50.1 104.595,50.219 104.597,50.227 104.599,50.236 104.6,50.245 104.6,50.254 104.599,50.263 104.598,50.271 104.595,50.28 104.595,50.281
LCD_D3 on TOP "TOP-LCD_D3 3" (solid, pour order 99): 26 vertices, not listed, extent 89.109,32.286 89.523,32.718
T_CS on TOP "TOP-T_CS" (solid, pour order 116): 26 vertices, not listed, extent 106.132,45.795 106.468,46.117
T_CS on TOP "TOP-T_CS 1" (solid, pour order 54): 25 vertices, not listed, extent 106.234,45.711 106.665,46.125
T_CS on TOP "TOP-T_CS 2" (solid, pour order 196): 115.58,28.771 115.725,28.652 116.525,28.802 115.725,28.952 115.58,28.833 115.578,28.825 115.576,28.816 115.575,28.807 115.575,28.798 115.576,28.79 115.577,28.781 115.58,28.772 115.58,28.771
T_CS on TOP "TOP-T_CS 3" (solid, pour order 164): 106.419,44.395 106.3,44.25 106.45,43.625 106.6,44.25 106.481,44.395 106.473,44.397 106.464,44.399 106.455,44.4 106.446,44.4 106.437,44.399 106.429,44.398 106.42,44.395 106.419,44.395
T_SCK on TOP "TOP-T_SCK" (solid, pour order 55): 25 vertices, not listed, extent 109.235,45.711 109.666,46.125
T_SCK on TOP "TOP-T_SCK 1" (solid, pour order 200): 21 vertices, not listed, extent 116.475,29.302 117.473,29.602
T_SCK on TOP "TOP-T_SCK 2" (solid, pour order 147): 109.481,42.905 109.6,43.05 109.45,43.675 109.3,43.05 109.419,42.905 109.427,42.903 109.436,42.901 109.445,42.9 109.454,42.9 109.463,42.901 109.471,42.902 109.48,42.905 109.481,42.905
T_SCK on TOP "TOP-T_SCK 3" (solid, pour order 167): 109.419,44.395 109.3,44.25 109.45,43.625 109.6,44.25 109.481,44.395 109.473,44.397 109.464,44.399 109.455,44.4 109.446,44.4 109.437,44.399 109.429,44.398 109.42,44.395 109.419,44.395
T_PEN on TOP "TOP-T_PEN" (solid, pour order 41): 25 vertices, not listed, extent 109.971,45.711 110.402,46.125
T_PEN on TOP "TOP-T_PEN 1" (solid, pour order 274): 29 vertices, not listed, extent 115.542,26.052 117.275,26.454
T_PEN on TOP "TOP-T_PEN 2" (solid, pour order 192): 117.42,26.233 117.275,26.352 116.475,26.202 117.275,26.052 117.42,26.171 117.422,26.18 117.424,26.188 117.425,26.197 117.425,26.206 117.424,26.215 117.423,26.224 117.42,26.232 117.42,26.233
T_PEN on TOP "TOP-T_PEN 3" (solid, pour order 179): 109.981,42.905 110.1,43.05 109.95,43.675 109.8,43.05 109.919,42.905 109.927,42.903 109.936,42.901 109.945,42.9 109.954,42.9 109.963,42.901 109.971,42.902 109.98,42.905 109.981,42.905
T_PEN on TOP "TOP-T_PEN 4" (solid, pour order 182): 109.919,44.395 109.8,44.25 109.95,43.625 110.1,44.25 109.981,44.395 109.973,44.397 109.964,44.399 109.955,44.4 109.946,44.4 109.937,44.399 109.929,44.398 109.92,44.395 109.919,44.395
T_MISO on TOP "TOP-T_MISO" (solid, pour order 43): 25 vertices, not listed, extent 110.708,45.711 111.139,46.125
T_MISO on TOP "TOP-T_MISO 1" (solid, pour order 273): 29 vertices, not listed, extent 115.542,26.702 117.275,27.104
T_MISO on TOP "TOP-T_MISO 2" (solid, pour order 142): 110.481,42.905 110.6,43.05 110.45,43.675 110.3,43.05 110.419,42.905 110.427,42.903 110.436,42.901 110.445,42.9 110.454,42.9 110.463,42.901 110.471,42.902 110.48,42.905 110.481,42.905
T_MISO on TOP "TOP-T_MISO 3" (solid, pour order 163): 110.419,44.395 110.3,44.25 110.45,43.625 110.6,44.25 110.481,44.395 110.473,44.397 110.464,44.399 110.455,44.4 110.446,44.4 110.437,44.399 110.429,44.398 110.42,44.395 110.419,44.395
T_MOSI on TOP "TOP-T_MOSI" (solid, pour order 45): 25 vertices, not listed, extent 111.444,45.711 111.875,46.125
T_MOSI on TOP "TOP-T_MOSI 1" (solid, pour order 195): 115.58,28.121 115.725,28.002 116.525,28.152 115.725,28.302 115.58,28.183 115.578,28.175 115.576,28.166 115.575,28.157 115.575,28.148 115.576,28.14 115.577,28.131 115.58,28.122 115.58,28.121
T_MOSI on TOP "TOP-T_MOSI 2" (solid, pour order 157): 110.981,42.905 111.1,43.05 110.95,43.675 110.8,43.05 110.919,42.905 110.927,42.903 110.936,42.901 110.945,42.9 110.954,42.9 110.963,42.901 110.971,42.902 110.98,42.905 110.981,42.905
T_MOSI on TOP "TOP-T_MOSI 3" (solid, pour order 166): 110.919,44.395 110.8,44.25 110.95,43.625 111.1,44.25 110.981,44.395 110.973,44.397 110.964,44.399 110.955,44.4 110.946,44.4 110.937,44.399 110.929,44.398 110.92,44.395 110.919,44.395
N17083179 on TOP "TOP-N17083179" (solid, pour order 305): 25 vertices, not listed, extent 25.019,83.963 26.221,85.124
N17083179 on TOP "TOP-N17083179 1" (solid, pour order 359): 21 vertices, not listed, extent 14.587,80.1 15.75,81.5
N17083179 on TOP "TOP-N17083179 2" (solid, pour order 286): 14.737,79.715 15.05,80.1 14.65,80.864 14.25,80.1 14.563,79.715 14.584,79.709 14.606,79.704 14.628,79.701 14.65,79.7 14.672,79.701 14.694,79.704 14.716,79.709 14.737,79.715
CTL_RELAY1 on TOP "TOP-CTL_RELAY1" (solid, pour order 202): 26 vertices, not listed, extent 80.4,78.017 80.902,78.65
CTL_RELAY1 on TOP "TOP-CTL_RELAY1 1" (solid, pour order 155): 112.981,42.905 113.1,43.05 112.95,43.675 112.8,43.05 112.919,42.905 112.927,42.903 112.936,42.901 112.945,42.9 112.954,42.9 112.963,42.901 112.971,42.902 112.98,42.905 112.981,42.905
CTL_RELAY2 on TOP "TOP-CTL_RELAY2" (solid, pour order 118): 23 vertices, not listed, extent 14.05,77.5 14.45,78.025
CTL_RELAY2 on TOP "TOP-CTL_RELAY2 1" (solid, pour order 9): 25 vertices, not listed, extent 14.085,77.175 14.516,77.589
CTL_RELAY2 on TOP "TOP-CTL_RELAY2 2" (solid, pour order 17): 25 vertices, not listed, extent 113.584,47.675 114.015,48.089
CTL_RELAY2 on TOP "TOP-CTL_RELAY2 3" (solid, pour order 153): 114.805,49.219 114.95,49.1 115.575,49.25 114.95,49.4 114.805,49.281 114.803,49.273 114.801,49.264 114.8,49.255 114.8,49.246 114.801,49.237 114.802,49.229 114.805,49.22 114.805,49.219
N17083894 on TOP "TOP-N17083894" (solid, pour order 288): 27 vertices, not listed, extent 131.35,77.09 132.653,77.791
N17083890 on TOP "TOP-N17083890" (solid, pour order 221): 22 vertices, not listed, extent 136.338,76.175 137.138,77
N17083890 on TOP "TOP-N17083890 1" (solid, pour order 204): 21 vertices, not listed, extent 134.475,77.09 135.35,77.69
N17083890 on TOP "TOP-N17083890 2" (solid, pour order 219): 22 vertices, not listed, extent 136.338,76.84 137.138,77.665
N17083890 on TOP "TOP-N17083890 3" (solid, pour order 280): 30 vertices, not listed, extent 135.688,77.24 136.763,78.04
N17083774 on TOP "TOP-N17083774" (solid, pour order 389): 38 vertices, not listed, extent 129.8,66.8 133,75.683
N17083776 on TOP "TOP-N17083776" (solid, pour order 290): 19 vertices, not listed, extent 133.95,74.64 135.05,75.553
N17083932 on TOP "TOP-N17083932" (solid, pour order 213): 22 vertices, not listed, extent 137.862,77.615 138.662,78.44
N17083932 on TOP "TOP-N17083932 1" (solid, pour order 217): 22 vertices, not listed, extent 137.862,78.3 138.662,79.125
VCC_12V_PUMP1 on TOP "TOP-VCC_12V_PUMP1" (solid, pour order 394): 149 vertices, not listed, extent 57,80.7 75.7,89.8
VCC_12V_PUMP2 on TOP "TOP-VCC_12V_PUMP2" (solid, pour order 393): 23 vertices, not listed, extent 24.4,80.5 42.9,89.5
GND on BOTTOM "BOTTOM-GND" (solid, pour order 416): -0.05,0 0,-0.05 150,-0.05 150.05,0 150.05,90 150,90.05 0,90.05 -0.05,90
GND on BOTTOM "BOTTOM-GND 1" (solid, pour order 397): 72 vertices, not listed, extent 29.526,20.359 87.341,25.169
GND on BOTTOM "BOTTOM-GND 2" (solid, pour order 379): 141 vertices, not listed, extent 25.059,45.331 27.951,47.807
GND on BOTTOM "BOTTOM-GND 3" (solid, pour order 384): 201 vertices, not listed, extent 24.159,48.437 27.332,59.831
GND on BOTTOM "BOTTOM-GND 4" (solid, pour order 414): 298 vertices, not listed, extent 29.455,37.481 76.291,64.743
GND on BOTTOM "BOTTOM-GND 5" (solid, pour order 391): 210 vertices, not listed, extent 91.439,33.061 98.939,65.604
GND on BOTTOM "BOTTOM-GND 6" (solid, pour order 402): 536 vertices, not listed, extent 81.743,26.065 97.941,71.241
GND on BOTTOM "BOTTOM-GND 7" (solid, pour order 411): 430 vertices, not listed, extent 24.159,16.959 108.341,46.895
GND on BOTTOM "BOTTOM-GND 8" (solid, pour order 409): 368 vertices, not listed, extent 29.529,27.321 82.241,70.663
VCC_3.3V on BOTTOM "BOTTOM-VCC_3.3V" (solid, pour order 386): 106.8,35.3 107.9,36.4 108.341,36.4 108.341,20.7 107.1,20.7 106.8,21 106.8,35.3
VCC_3.3V on BOTTOM "BOTTOM-VCC_3.3V 1" (solid, pour order 401): 18 vertices, not listed, extent 29.9,51.2 79.7,68.5
VCC_3.3V on BOTTOM "BOTTOM-VCC_3.3V 2" (solid, pour order 410): 77 vertices, not listed, extent 113.3,20.5 148.3,69.5
VCC_3.3V on BOTTOM "BOTTOM-VCC_3.3V 3" (solid, pour order 370): 26 vertices, not listed, extent 141.941,26.993 143.314,28.407
VCC_3.3V on BOTTOM "BOTTOM-VCC_3.3V 4" (solid, pour order 369): 25 vertices, not listed, extent 130.687,26.993 132.059,28.407
VCC_3.3V on BOTTOM "BOTTOM-VCC_3.3V 5" (solid, pour order 301): 25 vertices, not listed, extent 129.705,83.675 130.575,84.545
VCC_3.3V on BOTTOM "BOTTOM-VCC_3.3V 6" (solid, pour order 356): 26 vertices, not listed, extent 9.006,39.737 10.263,41.02
VCC_3.3V on BOTTOM "BOTTOM-VCC_3.3V 7" (solid, pour order 346): 25 vertices, not listed, extent 3.164,51.712 4.436,52.944
VCC_3.3V on BOTTOM "BOTTOM-VCC_3.3V 8" (solid, pour order 348): 25 vertices, not listed, extent 2.9,52.835 3.845,53.78
VCC_3.3V on BOTTOM "BOTTOM-VCC_3.3V 9" (solid, pour order 357): 26 vertices, not listed, extent 2.86,69.06 3.846,70.003
VCC_3.3V on BOTTOM "BOTTOM-VCC_3.3V 10" (solid, pour order 350): 25 vertices, not listed, extent 26.155,49.577 27.1,50.522
VCC_3.3V on BOTTOM "BOTTOM-VCC_3.3V 11" (solid, pour order 347): 25 vertices, not listed, extent 26.155,53.802 27.1,54.747
VCC_3.3V on BOTTOM "BOTTOM-VCC_3.3V 12" (solid, pour order 351): 25 vertices, not listed, extent 27.84,51.262 28.785,52.207
VCC_3.3V on BOTTOM "BOTTOM-VCC_3.3V 13" (solid, pour order 352): 25 vertices, not listed, extent 27.84,52.117 28.785,53.062
NRST on BOTTOM "BOTTOM-NRST" (solid, pour order 50): 25 vertices, not listed, extent 82.585,54.075 83.016,54.489
NRST on BOTTOM "BOTTOM-NRST 1" (solid, pour order 94): 25 vertices, not listed, extent 82.585,53.711 83.016,54.125
NRST on BOTTOM "BOTTOM-NRST 2" (solid, pour order 320): 25 vertices, not listed, extent 28.715,26.126 29.971,27.398
NRST on BOTTOM "BOTTOM-NRST 3" (solid, pour order 100): 25 vertices, not listed, extent 108.482,46.082 108.805,46.405
LED1 on BOTTOM "BOTTOM-LED1" (solid, pour order 29): 25 vertices, not listed, extent 7.485,29.011 7.916,29.425
LED1 on BOTTOM "BOTTOM-LED1 1" (solid, pour order 8): 25 vertices, not listed, extent 112.284,45.711 112.715,46.125
LCD_D15 on BOTTOM "BOTTOM-LCD_D15" (solid, pour order 32): 26 vertices, not listed, extent 85.175,53.087 85.589,53.518
LCD_D15 on BOTTOM "BOTTOM-LCD_D15 1" (solid, pour order 73): 26 vertices, not listed, extent 85.275,67.675 85.689,68.106
LCD_D14 on BOTTOM "BOTTOM-LCD_D14" (solid, pour order 56): 26 vertices, not listed, extent 85.175,52.286 85.589,52.717
LCD_D14 on BOTTOM "BOTTOM-LCD_D14 1" (solid, pour order 71): 26 vertices, not listed, extent 85.275,68.411 85.689,68.842
LCD_D6 on BOTTOM "BOTTOM-LCD_D6" (solid, pour order 331): 25 vertices, not listed, extent 26.182,34.364 27.1,35.282
LCD_D6 on BOTTOM "BOTTOM-LCD_D6 1" (solid, pour order 68): 26 vertices, not listed, extent 75.711,57.887 76.125,58.318
LCD_D12 on BOTTOM "BOTTOM-LCD_D12" (solid, pour order 40): 26 vertices, not listed, extent 85.175,50.687 85.589,51.117
LCD_D12 on BOTTOM "BOTTOM-LCD_D12 1" (solid, pour order 72): 26 vertices, not listed, extent 85.275,69.885 85.689,70.316
LCD_D7 on BOTTOM "BOTTOM-LCD_D7" (solid, pour order 318): 25 vertices, not listed, extent 28.715,36.286 29.971,37.558
LCD_D7 on BOTTOM "BOTTOM-LCD_D7 1" (solid, pour order 25): 26 vertices, not listed, extent 75.711,58.686 76.125,59.117
LCD_D5 on BOTTOM "BOTTOM-LCD_D5" (solid, pour order 315): 25 vertices, not listed, extent 28.715,33.746 29.971,35.018
LCD_D5 on BOTTOM "BOTTOM-LCD_D5 1" (solid, pour order 33): 26 vertices, not listed, extent 75.711,57.087 76.125,57.517
LCD_D11 on BOTTOM "BOTTOM-LCD_D11" (solid, pour order 115): 26 vertices, not listed, extent 85.175,49.886 85.591,50.317
LCD_D11 on BOTTOM "BOTTOM-LCD_D11 1" (solid, pour order 24): 26 vertices, not listed, extent 109.911,50.184 110.325,50.615
LCD_D9 on BOTTOM "BOTTOM-LCD_D9" (solid, pour order 92): 25 vertices, not listed, extent 84.985,46.075 85.416,46.489
LCD_D9 on BOTTOM "BOTTOM-LCD_D9 1" (solid, pour order 93): 25 vertices, not listed, extent 84.985,48.113 85.416,48.527
LCD_D1 on BOTTOM "BOTTOM-LCD_D1" (solid, pour order 316): 25 vertices, not listed, extent 28.715,28.666 29.971,29.938
LCD_D1 on BOTTOM "BOTTOM-LCD_D1 1" (solid, pour order 23): 26 vertices, not listed, extent 75.611,30.686 76.025,31.117
LCD_D1 on BOTTOM "BOTTOM-LCD_D1 2" (solid, pour order 80): 25 vertices, not listed, extent 89.475,30.686 89.889,31.117
LCD_D1 on BOTTOM "BOTTOM-LCD_D1 3" (solid, pour order 26): 26 vertices, not listed, extent 109.911,47.975 110.325,48.406
LCD_BL on BOTTOM "BOTTOM-LCD_BL" (solid, pour order 335): 25 vertices, not listed, extent 27.84,48.722 28.758,49.64
LCD_BL on BOTTOM "BOTTOM-LCD_BL 1" (solid, pour order 58): 26 vertices, not listed, extent 94.285,51.811 94.716,52.225
LCD_BL on BOTTOM "BOTTOM-LCD_BL 2" (solid, pour order 28): 26 vertices, not listed, extent 94.285,44.011 94.716,44.425
LCD_BL on BOTTOM "BOTTOM-LCD_BL 3" (solid, pour order 64): 26 vertices, not listed, extent 94.285,44.375 94.716,44.789
LCD_D0 on BOTTOM "BOTTOM-LCD_D0" (solid, pour order 330): 25 vertices, not listed, extent 26.182,26.744 27.1,27.662
LCD_D0 on BOTTOM "BOTTOM-LCD_D0 1" (solid, pour order 77): 26 vertices, not listed, extent 75.611,29.887 76.025,30.318
LCD_D0 on BOTTOM "BOTTOM-LCD_D0 2" (solid, pour order 27): 26 vertices, not listed, extent 109.911,47.238 110.325,47.669
LCD_D0 on BOTTOM "BOTTOM-LCD_D0 3" (solid, pour order 96): 25 vertices, not listed, extent 89.475,29.887 89.889,30.318
LCD_D10 on BOTTOM "BOTTOM-LCD_D10" (solid, pour order 19): 26 vertices, not listed, extent 85.175,49.087 85.589,49.518
LCD_D10 on BOTTOM "BOTTOM-LCD_D10 1" (solid, pour order 22): 26 vertices, not listed, extent 109.911,49.448 110.325,49.879
LCD_CS on BOTTOM "BOTTOM-LCD_CS" (solid, pour order 321): 25 vertices, not listed, extent 28.715,21.046 29.971,22.318
LCD_CS on BOTTOM "BOTTOM-LCD_CS 1" (solid, pour order 52): 25 vertices, not listed, extent 89.111,34.686 89.525,35.117
LCD_CS on BOTTOM "BOTTOM-LCD_CS 2" (solid, pour order 95): 25 vertices, not listed, extent 89.475,34.686 89.889,35.117
LCD_CS on BOTTOM "BOTTOM-LCD_CS 3" (solid, pour order 107): 25 vertices, not listed, extent 93.695,62.585 94.018,62.908
LCD_D13 on BOTTOM "BOTTOM-LCD_D13" (solid, pour order 70): 26 vertices, not listed, extent 85.175,51.487 85.589,51.918
LCD_D13 on BOTTOM "BOTTOM-LCD_D13 1" (solid, pour order 69): 26 vertices, not listed, extent 85.275,69.148 85.689,69.579
LCD_RS on BOTTOM "BOTTOM-LCD_RS" (solid, pour order 338): 25 vertices, not listed, extent 26.182,21.664 27.1,22.582
LCD_RS on BOTTOM "BOTTOM-LCD_RS 1" (solid, pour order 12): 25 vertices, not listed, extent 89.111,35.487 89.525,35.917
LCD_RS on BOTTOM "BOTTOM-LCD_RS 2" (solid, pour order 81): 25 vertices, not listed, extent 89.475,35.487 89.889,35.917
LCD_RS on BOTTOM "BOTTOM-LCD_RS 3" (solid, pour order 199): 34 vertices, not listed, extent 93.498,63.322 94.023,63.698
LCD_RD on BOTTOM "BOTTOM-LCD_RD" (solid, pour order 332): 25 vertices, not listed, extent 26.182,24.204 27.1,25.122
LCD_RD on BOTTOM "BOTTOM-LCD_RD 1" (solid, pour order 11): 25 vertices, not listed, extent 89.111,37.086 89.525,37.517
LCD_RD on BOTTOM "BOTTOM-LCD_RD 2" (solid, pour order 82): 25 vertices, not listed, extent 89.475,37.086 89.889,37.517
LCD_RD on BOTTOM "BOTTOM-LCD_RD 3" (solid, pour order 197): 34 vertices, not listed, extent 93.498,64.795 94.023,65.171
LCD_WR on BOTTOM "BOTTOM-LCD_WR" (solid, pour order 325): 25 vertices, not listed, extent 28.715,23.586 29.971,24.858
LCD_WR on BOTTOM "BOTTOM-LCD_WR 1" (solid, pour order 31): 25 vertices, not listed, extent 89.111,36.287 89.525,36.718
LCD_WR on BOTTOM "BOTTOM-LCD_WR 2" (solid, pour order 91): 25 vertices, not listed, extent 89.475,36.287 89.889,36.718
LCD_WR on BOTTOM "BOTTOM-LCD_WR 3" (solid, pour order 198): 34 vertices, not listed, extent 93.498,64.059 94.023,64.434
LCD_D2 on BOTTOM "BOTTOM-LCD_D2" (solid, pour order 333): 25 vertices, not listed, extent 26.182,29.284 27.1,30.202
